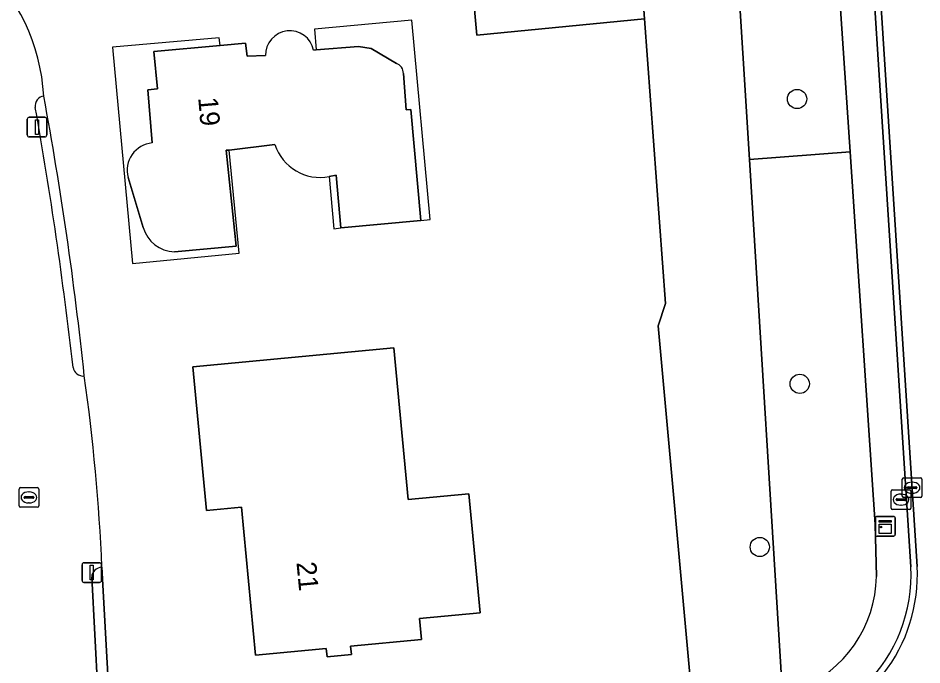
# Model space of a CAD drawing. Extents: x 162156 to 163172, y 378995 to 380779.
# Drawn here: x 162424.68 to 162470.62, y 380650.5 to 380683.37 of the extents above; entities that cross this region are included whole.
import ezdxf

# ---------------------------------------------------------------- set-up
doc = ezdxf.new("R2010")
doc.units = 0
for name, color, linetype in [('IMGEO_Berm_groen', 7, 'Continuous'), ('IMGEO_Boom', 7, 'Continuous'), ('IMGEO_Brandkraan', 7, 'Continuous'), ('IMGEO_Erf', 7, 'Continuous'), ('IMGEO_Groenvoorziening', 7, 'Continuous'), ('IMGEO_Kast', 7, 'Continuous'), ('IMGEO_Kolk', 7, 'Continuous'), ('IMGEO_Lichtmast', 7, 'Continuous'), ('IMGEO_Pand', 7, 'Continuous'), ('IMGEO_Pand_nummerreeks', 7, 'Continuous'), ('IMGEO_Pand_overbouw', 7, 'Continuous'), ('IMGEO_Rijbaan_lokaal_gesloten', 7, 'Continuous'), ('IMGEO_Rijbaan_lokaal_open', 7, 'Continuous'), ('IMGEO_Voetpad_open', 7, 'Continuous')]:
    doc.layers.add(name, color=color, linetype=linetype)

msp = doc.modelspace()

# ---------------------------------------------------------------- linework, layer by layer
at = {"layer": 'IMGEO_Berm_groen'}
msp.add_lwpolyline([(162465.803, 380693.874), (162463.409, 380693.714), (162463.288, 380695.51), (162465.682, 380695.67), (162465.326, 380700.959), (162462.919, 380698.497), (162460.932, 380697.44), (162460.5, 380697.81), (162461.859, 380676.176), (162466.966, 380676.574)], close=True, dxfattribs=at)
for points in [[(162466.966, 380676.574), (162461.859, 380676.176), (162463.528, 380649.012)], [(162468.3, 380655.001), (162468.239, 380657.63), (162466.966, 380676.574)]]:
    msp.add_lwpolyline(points, dxfattribs=at)
msp.add_arc((162462.051, 380655.085), 6.249, 291.1403, 359.2312, dxfattribs=at)
at = {"layer": 'IMGEO_Boom'}
for centre in [(162464.27, 380679.259), (162464.406, 380664.784), (162462.374, 380656.492)]:
    msp.add_circle(centre, 0.489, dxfattribs=at)
at = {"layer": 'IMGEO_Brandkraan'}
for p, q in [((162469.053, 380658.473), (162469.053, 380659.325)), ((162469.128, 380659.399), (162469.98, 380659.399)), ((162470.054, 380659.325), (162470.054, 380658.473)), ((162469.312, 380658.893), (162469.312, 380658.905)), ((162469.75, 380658.856), (162469.352, 380658.856)), ((162469.355, 380658.942), (162469.753, 380658.942)), ((162469.541, 380659.179), (162469.566, 380659.179)), ((162469.796, 380658.905), (162469.796, 380658.893)), ((162469.98, 380658.399), (162469.128, 380658.399)), ((162469.564, 380658.619), (162469.539, 380658.619))]:
    msp.add_line(p, q, dxfattribs=at)
for points in [[(162469.053, 380658.473), (162469.053, 380659.325)], [(162469.128, 380659.399), (162469.98, 380659.399)], [(162470.054, 380659.325), (162470.054, 380658.473)], [(162469.98, 380658.399), (162469.128, 380658.399)]]:
    msp.add_lwpolyline(points, dxfattribs=at)
for centre, radius, start, end in [((162469.13, 380659.323), 0.0765, 91.552, 178.448), ((162469.13, 380659.323), 0.0765, 91.552, 178.448), ((162469.978, 380659.323), 0.0765, 1.552, 88.448), ((162469.978, 380659.323), 0.0765, 1.552, 88.448), ((162469.352, 380658.902), 0.0403, 85.8775, 175.7526), ((162469.349, 380658.892), 0.0366, 178.938, 274.7102), ((162469.753, 380658.899), 0.043, 264.8664, 352.4533), ((162469.757, 380658.904), 0.0386, 1.7309, 96.639), ((162469.13, 380658.475), 0.0765, 181.552, 268.448), ((162469.13, 380658.475), 0.0765, 181.552, 268.448), ((162469.978, 380658.475), 0.0765, 271.552, 358.448), ((162469.978, 380658.475), 0.0765, 271.552, 358.448)]:
    msp.add_arc(centre, radius, start, end, dxfattribs=at)
for centre, major_axis, ratio, start_param, end_param in [((162469.54, 380658.899), (-0.387, 0.002), 0.722429, 4.712389, 7.853982), ((162469.565, 380658.899), (-0.39, 0.002), 0.717154, 1.570796, 4.712389)]:
    msp.add_ellipse(centre, major_axis=major_axis, ratio=ratio, start_param=start_param, end_param=end_param, dxfattribs=at)
at = {"layer": 'IMGEO_Erf'}
for points in [[(162428.941, 380655.461), (162429.47, 380645.75), (162430.568, 380645.853), (162458.951, 380648.521), (162457.215, 380667.736), (162457.588, 380668.862), (162456.516, 380683.328), (162448, 380682.5), (162447.59, 380687.025), (162456.195, 380687.817)], [(162431.496, 380677.026), (162431.266, 380679.728), (162431.768, 380679.769), (162431.577, 380681.675), (162434.952, 380681.977), (162436.242, 380682.092), (162436.323, 380681.429), (162437.251, 380681.461)], [(162439.699, 380681.742), (162439.821, 380681.752), (162441.973, 380681.922), (162442.622, 380681.826), (162443.902, 380681.069)], [(162444.262, 380680.552), (162444.405, 380678.702), (162444.632, 380678.72), (162445.141, 380673.086), (162441.089, 380672.703), (162440.841, 380675.386), (162440.489, 380675.325)], [(162437.733, 380676.94), (162435.408, 380676.665), (162435.249, 380676.65), (162435.753, 380671.787), (162432.622, 380671.49)], [(162431.041, 380672.733), (162430.274, 380675.272)]]:
    msp.add_lwpolyline(points, dxfattribs=at)
msp.add_lwpolyline([(162443.783, 380666.619), (162444.511, 380658.91), (162447.588, 380659.201), (162448.16, 380653.148), (162445.083, 380652.857), (162445.184, 380651.792), (162441.577, 380651.451), (162441.618, 380651.023), (162440.383, 380650.906), (162440.343, 380651.335), (162436.739, 380650.994), (162436.029, 380658.523), (162434.245, 380658.352), (162433.563, 380665.652)], close=True, dxfattribs=at)
for centre, radius, start, end in [((162415.913, 380678.811), 10.087, 3.3743, 89.9136), ((162438.488, 380681.487), 1.237, 11.9096, 181.1868), ((162443.72, 380680.559), 0.542, 359.3041, 70.3968), ((162246.554, 380646.154), 182.483, 5.98589, 10.49874), ((162431.612, 380675.642), 1.389, 94.8105, 195.4602), ((162440.014, 380677.673), 2.396, 197.8253, 281.4346), ((162432.668, 380673.176), 1.686, 195.2224, 268.428), ((162327.094, 380650.947), 101.947, 2.53768, 8.02755)]:
    msp.add_arc(centre, radius, start, end, dxfattribs=at)
at = {"layer": 'IMGEO_Groenvoorziening'}
msp.add_lwpolyline([(162463.528, 380649.012), (162461.859, 380676.176), (162460.5, 380697.81), (162460.213, 380698.056), (162455.268, 380702.293), (162456.195, 380687.817), (162456.516, 380683.328), (162457.588, 380668.862), (162457.215, 380667.736), (162458.951, 380648.521), (162462.393, 380648.844)], dxfattribs=at)
at = {"layer": 'IMGEO_Kast'}
for p, q in [((162468.255, 380657.12), (162468.255, 380657.961)), ((162468.255, 380657.961), (162468.255, 380657.12)), ((162468.33, 380658.045), (162469.171, 380658.045)), ((162469.171, 380658.045), (162468.33, 380658.045)), ((162469.255, 380657.97), (162469.255, 380657.129)), ((162469.255, 380657.129), (162469.255, 380657.97)), ((162469.18, 380657.045), (162468.339, 380657.045)), ((162468.339, 380657.045), (162469.18, 380657.045))]:
    msp.add_line(p, q, dxfattribs=at)
for points in [[(162468.45, 380657.835), (162469.05, 380657.835), (162469.05, 380657.75), (162468.45, 380657.75), (162468.45, 380657.835)], [(162468.45, 380657.66), (162469.05, 380657.66), (162469.05, 380657.171), (162468.45, 380657.171), (162468.45, 380657.66)]]:
    msp.add_lwpolyline(points, dxfattribs=at)
msp.add_circle((162468.534, 380657.509), 0.0377, dxfattribs=at)
for centre, start, end in [((162468.333, 380657.967), 92.4484, 184.2845), ((162468.333, 380657.967), 92.4484, 184.2845), ((162469.177, 380657.967), 2.4484, 94.2845), ((162469.177, 380657.967), 2.4484, 94.2845), ((162468.333, 380657.123), 182.4484, 274.2845), ((162468.333, 380657.123), 182.4484, 274.2845), ((162469.177, 380657.123), 272.4484, 4.2845), ((162469.177, 380657.123), 272.4484, 4.2845)]:
    msp.add_arc(centre, 0.0779, start, end, dxfattribs=at)
at = {"layer": 'IMGEO_Kolk'}
for p, q in [((162469.614, 380659.08), (162469.614, 380659.932)), ((162469.689, 380660.006), (162470.541, 380660.006)), ((162470.102, 380659.786), (162470.127, 380659.786)), ((162470.615, 380659.932), (162470.615, 380659.08)), ((162424.728, 380658.586), (162424.728, 380659.438)), ((162424.803, 380659.512), (162425.655, 380659.512)), ((162425.216, 380659.292), (162425.241, 380659.292)), ((162425.729, 380659.438), (162425.729, 380658.586)), ((162469.873, 380659.5), (162469.873, 380659.512)), ((162470.311, 380659.463), (162469.913, 380659.463)), ((162469.916, 380659.549), (162470.314, 380659.549)), ((162470.125, 380659.226), (162470.1, 380659.226)), ((162470.357, 380659.512), (162470.357, 380659.5)), ((162424.987, 380659.006), (162424.987, 380659.018)), ((162425.425, 380658.969), (162425.027, 380658.969)), ((162425.03, 380659.055), (162425.428, 380659.055)), ((162425.239, 380658.732), (162425.214, 380658.732)), ((162425.471, 380659.018), (162425.471, 380659.006)), ((162470.541, 380659.006), (162469.689, 380659.006)), ((162425.655, 380658.512), (162424.803, 380658.512))]:
    msp.add_line(p, q, dxfattribs=at)
for points in [[(162469.614, 380659.08), (162469.614, 380659.932)], [(162469.689, 380660.006), (162470.541, 380660.006)], [(162470.615, 380659.932), (162470.615, 380659.08)], [(162424.728, 380658.586), (162424.728, 380659.438)], [(162424.803, 380659.512), (162425.655, 380659.512)], [(162425.729, 380659.438), (162425.729, 380658.586)], [(162470.541, 380659.006), (162469.689, 380659.006)], [(162425.655, 380658.512), (162424.803, 380658.512)]]:
    msp.add_lwpolyline(points, dxfattribs=at)
for centre, radius, start, end in [((162469.691, 380659.93), 0.0765, 91.552, 178.448), ((162469.691, 380659.93), 0.0765, 91.552, 178.448), ((162470.539, 380659.93), 0.0765, 1.552, 88.448), ((162470.539, 380659.93), 0.0765, 1.552, 88.448), ((162424.805, 380659.436), 0.0765, 91.552, 178.448), ((162424.805, 380659.436), 0.0765, 91.552, 178.448), ((162425.653, 380659.436), 0.0765, 1.552, 88.448), ((162425.653, 380659.436), 0.0765, 1.552, 88.448), ((162469.913, 380659.509), 0.0403, 85.8775, 175.7526), ((162469.91, 380659.499), 0.0366, 178.938, 274.7102), ((162470.314, 380659.506), 0.043, 264.8664, 352.4533), ((162470.318, 380659.511), 0.0386, 1.7309, 96.639), ((162425.027, 380659.015), 0.0403, 85.8775, 175.7526), ((162425.024, 380659.005), 0.0366, 178.938, 274.7102), ((162425.428, 380659.012), 0.043, 264.8664, 352.4533), ((162425.432, 380659.017), 0.0386, 1.7309, 96.639), ((162469.691, 380659.082), 0.0765, 181.552, 268.448), ((162469.691, 380659.082), 0.0765, 181.552, 268.448), ((162470.539, 380659.082), 0.0765, 271.552, 358.448), ((162470.539, 380659.082), 0.0765, 271.552, 358.448), ((162424.805, 380658.588), 0.0765, 181.552, 268.448), ((162424.805, 380658.588), 0.0765, 181.552, 268.448), ((162425.653, 380658.588), 0.0765, 271.552, 358.448), ((162425.653, 380658.588), 0.0765, 271.552, 358.448)]:
    msp.add_arc(centre, radius, start, end, dxfattribs=at)
for centre, major_axis, ratio, start_param, end_param in [((162470.101, 380659.506), (-0.387, 0.002), 0.722429, 4.712389, 7.853982), ((162470.126, 380659.506), (-0.39, 0.002), 0.717154, 1.570796, 4.712389), ((162425.215, 380659.012), (-0.387, 0.002), 0.722429, 4.712389, 7.853982), ((162425.24, 380659.012), (-0.39, 0.002), 0.717154, 1.570796, 4.712389)]:
    msp.add_ellipse(centre, major_axis=major_axis, ratio=ratio, start_param=start_param, end_param=end_param, dxfattribs=at)
at = {"layer": 'IMGEO_Lichtmast'}
for p, q in [((162425.141, 380677.429), (162425.141, 380678.229)), ((162425.141, 380678.229), (162425.141, 380677.429)), ((162425.241, 380678.329), (162426.031, 380678.329)), ((162426.031, 380678.329), (162425.241, 380678.329)), ((162426.131, 380678.229), (162426.131, 380677.429)), ((162426.131, 380677.429), (162426.131, 380678.229)), ((162426.031, 380677.329), (162425.241, 380677.329)), ((162425.241, 380677.329), (162426.031, 380677.329)), ((162427.927, 380654.791), (162427.927, 380655.591)), ((162427.927, 380655.591), (162427.927, 380654.791)), ((162428.027, 380655.691), (162428.817, 380655.691)), ((162428.817, 380655.691), (162428.027, 380655.691)), ((162428.917, 380655.591), (162428.917, 380654.791)), ((162428.917, 380654.791), (162428.917, 380655.591)), ((162428.817, 380654.691), (162428.027, 380654.691)), ((162428.027, 380654.691), (162428.817, 380654.691))]:
    msp.add_line(p, q, dxfattribs=at)
for points in [[(162425.561, 380678.204), (162425.711, 380678.204), (162425.711, 380677.454), (162425.561, 380677.454), (162425.561, 380678.204)], [(162428.347, 380655.566), (162428.497, 380655.566), (162428.497, 380654.816), (162428.347, 380654.816), (162428.347, 380655.566)]]:
    msp.add_lwpolyline(points, dxfattribs=at)
for centre, start, end in [((162425.241, 380678.229), 90, 180), ((162425.241, 380678.229), 90, 180), ((162426.031, 380678.229), 0, 90), ((162426.031, 380678.229), 360, 90), ((162425.241, 380677.429), 180, 270), ((162425.241, 380677.429), 180, 270), ((162426.031, 380677.429), 270, 0), ((162426.031, 380677.429), 270, 0), ((162428.027, 380655.591), 90, 180), ((162428.027, 380655.591), 90, 180), ((162428.817, 380655.591), 0, 90), ((162428.817, 380655.591), 360, 90), ((162428.027, 380654.791), 180, 270), ((162428.027, 380654.791), 180, 270), ((162428.817, 380654.791), 270, 0), ((162428.817, 380654.791), 270, 0)]:
    msp.add_arc(centre, 0.1, start, end, dxfattribs=at)
at = {"layer": 'IMGEO_Pand'}
for points in [[(162456.195, 380687.817), (162447.59, 380687.025), (162448, 380682.5), (162456.516, 380683.328)], [(162440.383, 380650.906), (162441.618, 380651.023), (162441.577, 380651.451), (162445.184, 380651.792), (162445.083, 380652.857), (162448.16, 380653.148), (162447.588, 380659.201), (162444.511, 380658.91), (162443.783, 380666.619), (162433.563, 380665.652), (162434.245, 380658.352), (162436.029, 380658.523), (162436.739, 380650.994), (162440.343, 380651.335)]]:
    msp.add_lwpolyline(points, close=True, dxfattribs=at)
for points in [[(162437.251, 380681.461), (162436.323, 380681.429), (162436.242, 380682.092), (162434.952, 380681.977), (162431.577, 380681.675), (162431.768, 380679.769), (162431.266, 380679.728), (162431.496, 380677.026)], [(162443.902, 380681.069), (162442.622, 380681.826), (162441.973, 380681.922), (162439.821, 380681.752), (162439.699, 380681.742)], [(162440.489, 380675.325), (162440.841, 380675.386), (162441.089, 380672.703), (162445.141, 380673.086), (162444.632, 380678.72), (162444.405, 380678.702), (162444.262, 380680.552)], [(162432.622, 380671.49), (162435.753, 380671.787), (162435.249, 380676.65), (162435.408, 380676.665), (162437.733, 380676.94)], [(162430.274, 380675.272), (162431.041, 380672.733)]]:
    msp.add_lwpolyline(points, dxfattribs=at)
for centre, radius, start, end in [((162438.488, 380681.487), 1.237, 11.9096, 181.1868), ((162443.72, 380680.559), 0.542, 359.3041, 70.3968), ((162431.612, 380675.642), 1.389, 94.8105, 195.4602), ((162440.014, 380677.673), 2.396, 197.8253, 281.4346), ((162432.668, 380673.176), 1.686, 195.2224, 268.428)]:
    msp.add_arc(centre, radius, start, end, dxfattribs=at)
at = {"layer": 'IMGEO_Pand_overbouw'}
for points in [[(162445.141, 380673.086), (162445.618, 380673.129), (162444.682, 380683.268), (162439.737, 380682.815), (162439.821, 380681.752), (162441.973, 380681.922), (162442.622, 380681.826), (162443.902, 380681.069)], [(162434.952, 380681.977), (162434.89, 380682.373), (162429.472, 380681.889), (162430.495, 380670.904), (162435.907, 380671.419), (162435.408, 380676.665), (162435.249, 380676.65), (162435.753, 380671.787), (162432.622, 380671.49)], [(162431.496, 380677.026), (162431.266, 380679.728), (162431.768, 380679.769), (162431.577, 380681.675), (162434.952, 380681.977)], [(162444.262, 380680.552), (162444.405, 380678.702), (162444.632, 380678.72), (162445.141, 380673.086)], [(162431.041, 380672.733), (162430.274, 380675.272)]]:
    msp.add_lwpolyline(points, dxfattribs=at)
msp.add_lwpolyline([(162441.089, 380672.703), (162440.841, 380675.386), (162440.489, 380675.325), (162440.722, 380672.666)], close=True, dxfattribs=at)
for centre, radius, start, end in [((162443.72, 380680.559), 0.542, 359.3041, 70.3968), ((162431.612, 380675.642), 1.389, 94.8105, 195.4602), ((162432.668, 380673.176), 1.686, 195.2224, 268.428)]:
    msp.add_arc(centre, radius, start, end, dxfattribs=at)
at = {"layer": 'IMGEO_Rijbaan_lokaal_gesloten'}
for points in [[(162465.726, 380726.893), (162466.035, 380722.933), (162466.173, 380720.592), (162466.581, 380713.671), (162466.903, 380709.429), (162470.372, 380655.509)], [(162466.903, 380709.429), (162466.581, 380713.671), (162466.173, 380720.592), (162465.884, 380720.286), (162466.582, 380709.432), (162470.053, 380655.488)], [(162470.372, 380655.509), (162466.903, 380709.429)]]:
    msp.add_lwpolyline(points, dxfattribs=at)
for centre, radius, start, end in [((162462.181, 380655.077), 8.202, 322.0843, 3.017), ((162462.181, 380655.077), 8.202, 322.0843, 3.017), ((162462.163, 380655.084), 7.901, 314.5776, 2.9343)]:
    msp.add_arc(centre, radius, start, end, dxfattribs=at)
at = {"layer": 'IMGEO_Rijbaan_lokaal_open'}
msp.add_lwpolyline([(162428.887, 380646.222), (162428.42, 380654.952)], dxfattribs=at)
for centre, radius, start, end in [((162415.913, 380678.811), 10.087, 3.3743, 89.9136), ((162426.037, 380678.916), 0.492, 96.4235, 189.6122), ((162215.853, 380641.664), 212.968, 6.45884, 10.0514), ((162427.985, 380665.703), 0.523, 189.0713, 276.2666), ((162327.094, 380650.947), 101.947, 2.53768, 8.02755), ((162428.941, 380654.94), 0.521, 89.9632, 178.7018)]:
    msp.add_arc(centre, radius, start, end, dxfattribs=at)
at = {"layer": 'IMGEO_Voetpad_open'}
for points in [[(162464.732, 380709.797), (162465.038, 380705.25), (162465.326, 380700.959), (162465.682, 380695.67), (162463.288, 380695.51), (162463.409, 380693.714), (162465.803, 380693.874), (162466.966, 380676.574), (162468.239, 380657.63), (162468.3, 380655.001)], [(162470.053, 380655.488), (162466.582, 380709.432)], [(162429.47, 380645.75), (162428.941, 380655.461)], [(162428.42, 380654.952), (162428.887, 380646.222)]]:
    msp.add_lwpolyline(points, dxfattribs=at)
for centre, radius, start, end in [((162426.037, 380678.916), 0.492, 96.4235, 189.6122), ((162246.554, 380646.154), 182.483, 5.98589, 10.49874), ((162215.853, 380641.664), 212.968, 6.45884, 10.0514), ((162427.985, 380665.703), 0.523, 189.0713, 276.2666), ((162428.941, 380654.94), 0.521, 89.9632, 178.7018), ((162462.163, 380655.084), 7.901, 314.5776, 2.9343), ((162462.051, 380655.085), 6.249, 291.1403, 359.2312)]:
    msp.add_arc(centre, radius, start, end, dxfattribs=at)

# ---------------------------------------------------------------- texts
at = {"layer": 'IMGEO_Pand_nummerreeks'}
for s, rotation, p in [('19', 274.8654, (162433.83, 380679.324)), ('21', 275.3872, (162438.825, 380655.706))]:
    msp.add_text(s, height=1, rotation=rotation, dxfattribs=at).set_placement(p)

doc.saveas('drawing.dxf')
